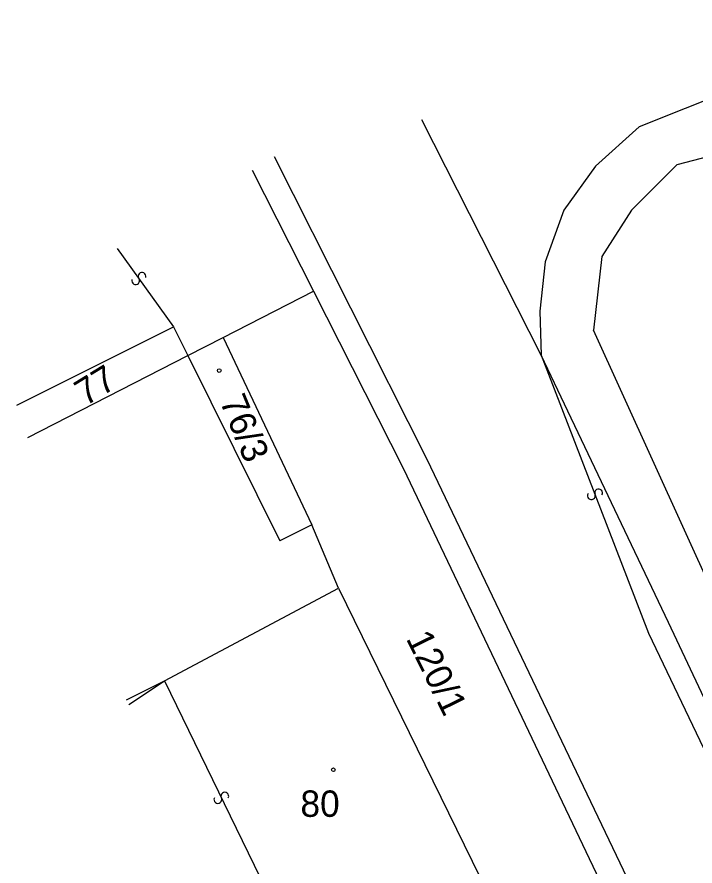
# Model space of a CAD drawing. Extents: x -595692 to -595466, y -1166896 to -1166788.
# Drawn here: x -595692.47 to -595660.34, y -1166845.7 to -1166805.48 of the extents above; entities that cross this region are included whole.
import ezdxf

# ---------------------------------------------------------------- set-up
doc = ezdxf.new("R2010")
doc.units = 0
doc.layers.add('DKM Holásky M 1_500', color=7, linetype='Continuous')

msp = doc.modelspace()

# ---------------------------------------------------------------- linework, layer by layer
at = {"layer": 'DKM Holásky M 1_500'}
for points in [[(-595649.91, -1166805.48), (-595662.99, -1166810.69)], [(-595648.15, -1166809.09), (-595661.2, -1166812.49)], [(-595667.63, -1166821.5), (-595673.287, -1166810.347)], [(-595662.99, -1166810.69), (-595665.05, -1166812.55)], [(-595673.03, -1166826.45), (-595680.271, -1166812.105)], [(-595681.331, -1166812.73), (-595678.42, -1166818.47)], [(-595665.05, -1166812.55), (-595666.56, -1166814.63)], [(-595661.2, -1166812.49), (-595663.35, -1166814.63)], [(-595666.56, -1166814.63), (-595667.44, -1166817.08)], [(-595663.35, -1166814.63), (-595664.76, -1166816.83)], [(-595687.729, -1166816.44), (-595685.05, -1166820.15)], [(-595667.44, -1166817.08), (-595667.7, -1166819.41)], [(-595664.76, -1166816.83), (-595665.15, -1166820.32)], [(-595682.7, -1166820.66), (-595678.42, -1166818.47)], [(-595678.42, -1166818.47), (-595674.15, -1166826.88)], [(-595667.7, -1166819.41), (-595667.63, -1166821.5)], [(-595692.474, -1166823.87), (-595685.05, -1166820.15)], [(-595685.05, -1166820.15), (-595684.37, -1166821.52)], [(-595659.48, -1166832.78), (-595665.15, -1166820.32)], [(-595684.37, -1166821.52), (-595682.7, -1166820.66)], [(-595682.7, -1166820.66), (-595678.5, -1166829.54)], [(-595691.966, -1166825.401), (-595684.37, -1166821.52)], [(-595684.37, -1166821.52), (-595680.02, -1166830.3)], [(-595667.63, -1166821.5), (-595662.54, -1166834.67)], [(-595661.59, -1166834.17), (-595667.63, -1166821.5)], [(-595644.41, -1166886.28), (-595673.03, -1166826.45)], [(-595674.15, -1166826.88), (-595645.66, -1166886.67)], [(-595678.5, -1166829.54), (-595680.02, -1166830.3)], [(-595677.24, -1166832.53), (-595678.5, -1166829.54)], [(-595685.49, -1166836.93), (-595677.24, -1166832.53)], [(-595677.24, -1166832.53), (-595670.16, -1166846.99)], [(-595638.25, -1166883.67), (-595661.59, -1166834.17)], [(-595662.54, -1166834.67), (-595638.93, -1166884.03)], [(-595687.29, -1166837.828), (-595685.49, -1166836.93)], [(-595687.179, -1166838.054), (-595685.49, -1166836.93)], [(-595685.49, -1166836.93), (-595680.09, -1166848)]]:
    msp.add_lwpolyline(points, dxfattribs=at)
for centre in [(-595682.89, -1166822.23), (-595677.48, -1166841.14)]:
    msp.add_circle(centre, 0.0875, dxfattribs=at)
for centre, start, end in [((-595686.55, -1166817.763), 342.94, 215.5032), ((-595686.851, -1166817.976), 162.9443, 35.1599), ((-595665.253, -1166828.154), 148.5569, 19.6925), ((-595664.908, -1166828.025), 328.5098, 200.7035), ((-595682.956, -1166842.549), 153.5752, 24.8918), ((-595682.624, -1166842.39), 333.1852, 205.7323)]:
    msp.add_arc(centre, 0.184, start, end, dxfattribs=at)

# ---------------------------------------------------------------- texts
for s, rotation, p in [('77', 31.5003, (-595689.234, -1166823.935)), ('76/3', 292.5023, (-595682.88, -1166823.674)), ('120/1', 296.1024, (-595674.053, -1166834.921))]:
    msp.add_text(s, height=1.25, rotation=rotation, dxfattribs=at).set_placement(p)
msp.add_text('80', height=1.25, dxfattribs=at).set_placement((-595679.04, -1166843.37))

doc.saveas('drawing.dxf')
